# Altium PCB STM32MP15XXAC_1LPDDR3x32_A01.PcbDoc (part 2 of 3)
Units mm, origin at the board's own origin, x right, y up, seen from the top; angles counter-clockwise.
Board outline 89 x 120 mm, 6 copper layers (Top Layer, Signal Layer 1, Signal Layer 2, Signal Layer 3, Signal Layer 4, Bottom Layer), stack 1.556 mm thick; 93 components, 99 nets, 917 pads, 464 vias.
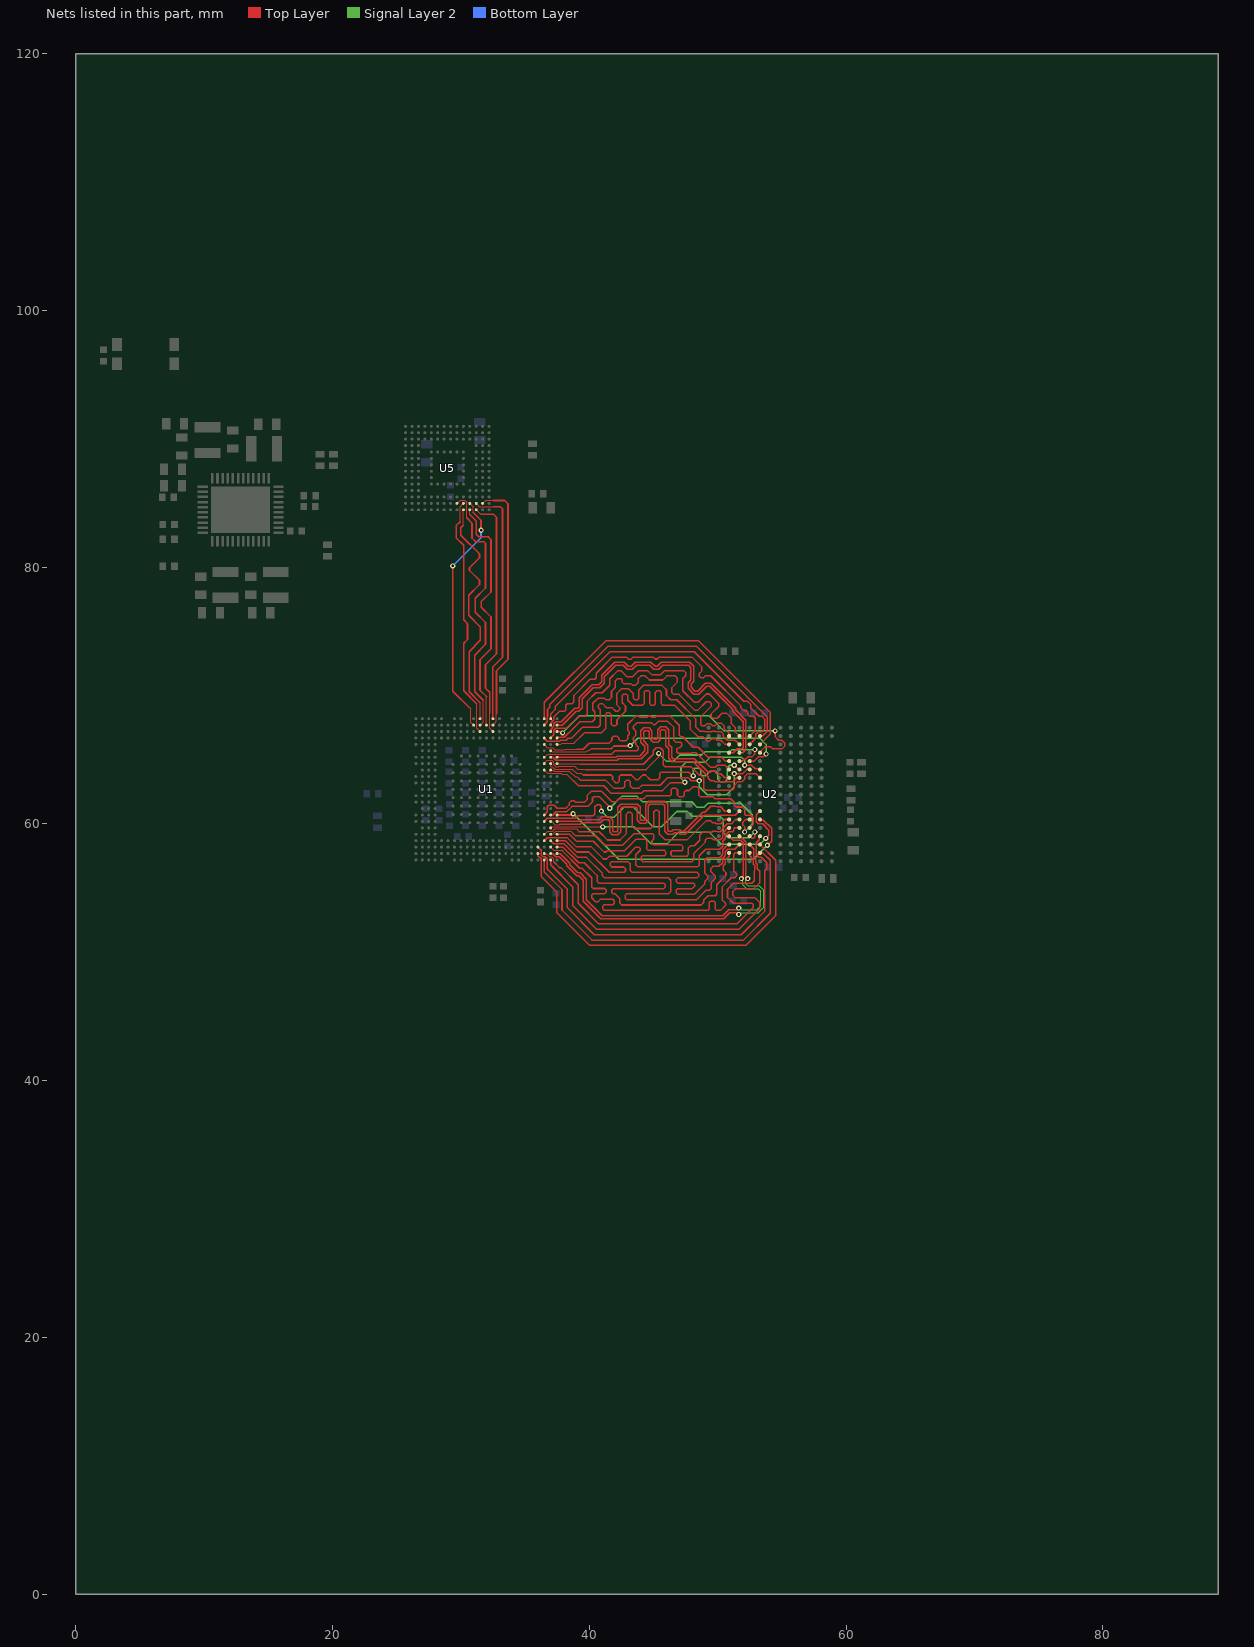
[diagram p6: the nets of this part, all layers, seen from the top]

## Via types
v1: diameter 0.4, hole 0.2, Top Layer to Bottom Layer, tented both sides, 258 vias
v2: diameter 0.25, hole 0.1, Top Layer to Signal Layer 1, tented top, 105 vias
v3: diameter 0.6, hole 0.3, Top Layer to Bottom Layer, tented both sides, 95 vias
v4: diameter 0.25, hole 0.1, Top Layer to Signal Layer 1, tented both sides, 6 vias

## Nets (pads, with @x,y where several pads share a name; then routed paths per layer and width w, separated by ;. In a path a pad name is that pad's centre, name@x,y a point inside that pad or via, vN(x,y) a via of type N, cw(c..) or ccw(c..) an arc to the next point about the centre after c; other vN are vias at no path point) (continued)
DDR_DQ1: U1.F22 U2.N9 | length 19.7
  Top Layer w0.09: U1.F22@37,65.7 37.089,65.611 39.773,65.611 39.908,65.746 40.055,65.746 40.17,65.861
  Top Layer w0.12: 40.17,65.861 41.711,65.861 41.925,66.075 43.175,66.075 v1(43.2,66.1) ; U2.N9@52.5,64.9 52.847,64.9 53.172,65.225 53.55,65.225 v1(53.775,65.45)
  Signal Layer 2 w0.12: v1(43.2,66.1) 43.775,66.675 53.3,66.675 53.775,66.2 v1(53.775,65.45)
DDR_DQ2: U1.H21 U2.N10 | length 20.1
  Top Layer w0.09: U1.H21@36.5,64.7 36.75,64.95 37.1,64.95 37.25,64.8 37.25,64.599 37.398,64.451 37.601,64.451 37.646,64.496 38.885,64.496 39.105,64.276 39.635,64.276 39.676,64.235
  Top Layer w0.12: 39.676,64.235 44.425,64.235 45.4,65.21 v1(45.4,65.5) v1@45.4,65.525 ; U2.N10@51.7,64.9 51.916,64.9 52.041,65.025 52.15,65.025 52.35,65.225 52.675,65.225 52.9,65.45 v1(52.9,65.8)
  Signal Layer 2 w0.12: v1(45.4,65.5) 46.025,64.875 46.55,64.875 47.05,65.375 48.75,65.375 48.991,65.616 50.941,65.616 51.125,65.8 v1(52.9,65.8)
DDR_DQ3: U1.E21 U2.N11 | length 19
  Top Layer w0.09: U1.E21@36.5,66.196 36.75,65.946 37.163,65.946 37.328,65.781 38.131,65.781 38.171,65.821 39.046,65.821
  Top Layer w0.12: 39.046,65.821 39.536,65.821 39.995,66.28 ; 39.995,66.281 41.537,66.281 41.775,66.519 41.775,66.725 41.875,66.825 42.2,66.825 42.3,66.725 42.3,66.598 42.403,66.495 42.875,66.495 43,66.62 43,66.869 43.128,66.997 43.128,67.153 43.005,67.276 43.005,67.774 43.641,68.41 43.85,68.41 43.95,68.31 44.485,68.31 44.585,68.41 44.79,68.41 44.89,68.31 45.111,68.31 45.211,68.41 46.299,68.41 47.02,67.689 47.02,66.925 47.15,66.795 47.279,66.795 48.104,65.97 48.492,65.97 49.277,65.185 49.901,65.185 49.936,65.22 50.28,65.22 50.6,64.9 U2.N11@50.9,64.9
DDR_DQ4: U1.J21 U2.M8 | length 20.5
  Top Layer w0.09: U1.J21@36.5,64.196 36.755,63.941 37.82,63.941 37.87,63.891 38.259,63.891 38.775,63.375
  Top Layer w0.12: 38.775,63.375 39.175,62.975 41.127,62.975 41.722,62.38 44.056,62.38 44.281,62.605 45.711,62.605 46.301,63.195 47.395,63.195 v1(47.45,63.25) ; v1(52.1,64.575) 52.65,64.575 52.925,64.3 53.25,64.3 U2.M8@53.3,64.25
  Signal Layer 2 w0.12: v1(47.45,63.25) 47.15,63.55 47.15,64.425 47.525,64.8 49.011,64.8 49.399,65.189 51.886,65.189 52.1,64.975 v1(52.1,64.575)
DDR_DQ5: U1.J22 U2.M9 | length 19.6
  Top Layer w0.09: U1.J22@37,64.186 37.183,64.186 37.258,64.111 38.449,64.111 38.895,63.665 39.079,63.665 39.194,63.55
  Top Layer w0.12: 39.194,63.55 39.349,63.395 41.301,63.395 41.896,62.8 42.65,62.8 42.77,62.92 42.77,63.295 42.87,63.395 43.105,63.395 43.2,63.3 43.2,62.95 43.35,62.8 43.882,62.8 44.107,63.025 45.525,63.025 46.115,63.615 47.71,63.615 47.95,63.375 v1(48.575,63.375) ; v1(51.3,63.925) 51.959,63.925 52.284,64.25 U2.M9@52.5,64.25
  Signal Layer 2 w0.12: v1(48.575,63.375) 48.575,62.9 49.2,62.275 50.7,62.275 51.3,62.875 v1(51.3,63.925)
DDR_DQ6: U1.H22 U2.M10 | length 20
  Top Layer w0.09: U1.H22@37,64.7 37,64.5 37.06,64.44 37.11,64.44 37.174,64.376 37.233,64.376 37.328,64.281 38.69,64.281 39.015,63.955 39.383,63.955 39.523,63.815
  Top Layer w0.12: 39.523,63.815 41.71,63.815 41.815,63.71 41.815,63.475 42.07,63.22 42.225,63.22 42.35,63.345 42.35,63.7 42.465,63.815 43.279,63.815 43.649,63.445 43.795,63.445 44.165,63.815 44.385,63.815 44.755,63.445 45.351,63.445 45.503,63.597 45.5,63.6 45.5,63.925 45.61,64.035 47.75,64.035 ; 47.751,64.036 v1@48.044,63.744 ; v1(51.3,64.575) 51.625,64.25 U2.M10@51.7,64.25
  Signal Layer 2 w0.12: v1(48.1,63.75) 48.1,64.223 48.227,64.35 48.575,64.35 48.7,64.225 48.7,63.875 48.825,63.75 49.05,63.75 49.425,64.125 49.861,64.125 50.025,63.961 50.025,63.475 50.225,63.275 50.55,63.275 50.75,63.475 50.75,64.375 50.95,64.575 v1(51.3,64.575)
DDR_DQ7: U1.G21 U2.M11 | length 20.7
  Top Layer w0.09: U1.G21@36.515,65.196 36.76,65.441 40.15,65.441
  Top Layer w0.12: 40.15,65.441 41.74,65.441 42.004,65.705 43.725,65.705 43.825,65.805 43.825,65.988 43.61,66.203 43.61,66.375 43.425,66.56 43.425,66.7 43.61,66.885 43.61,67.265 43.425,67.45 43.425,67.6 43.715,67.89 44.848,67.89 44.998,67.74 45.135,67.74 45.385,67.99 46.125,67.99 46.6,67.515 46.6,66.53 46.755,66.375 47.105,66.375 47.215,66.265 47.215,66.09 47.075,65.95 46.945,65.95 46.82,65.825 46.82,65.625 46.939,65.506 47.976,65.506 48.02,65.55 48.316,65.55 49.35,64.516 49.451,64.415 49.815,64.415 49.975,64.575 50.575,64.575 U2.M11@50.9,64.25
DDR_DQ8: U1.T21 U2.E9 | length 22.4
  Top Layer w0.1: U1.T21@36.5,60.7 36.75,60.95 36.75,61.35 36.85,61.45 37.29,61.45 37.525,61.215 ; 52.175,60.675 52.585,60.675 52.79,60.47 52.79,59.99 U2.E9@52.5,59.7
  Top Layer w0.12: 37.525,61.215 38.175,61.215 38.435,61.475 38.435,61.631 38.614,61.81 38.825,61.81 38.935,61.7 39.63,61.7 39.835,61.905 39.835,62.21 40.18,62.555 40.953,62.555 41.792,61.717 42.062,61.717 42.305,61.96 44.23,61.96 44.455,62.185 46.285,62.185 46.375,62.275 46.375,62.675 46.475,62.775 46.775,62.775 46.875,62.675 46.875,62.25 46.99,62.135 47.325,62.135 47.39,62.2 47.39,62.465 47.535,62.61 47.785,62.61 48.079,62.904 48.4,62.904 48.516,62.788 48.516,62.284 48.665,62.135 49.63,62.135 ; 49.657,62.11 49.632,62.135 49.63,62.135 ; 51.305,61.465 51.305,61.698 51.028,61.975 49.79,61.975 49.63,62.135 ; 51.307,61.463 51.445,61.325 51.9,61.325 52.1,61.125 52.1,60.75 52.175,60.675
DDR_DQ9: U1.U21 U2.D9 | length 21.8
  Top Layer w0.1: U1.U21@36.5,60.196 36.502,60.198 36.75,60.446 38.9,60.446 39.104,60.65 40.3,60.65 40.45,60.8 40.45,61.332 40.613,61.496 40.825,61.496 40.95,61.371 v1(40.95,61)
  Top Layer w0.12: U2.D9@52.5,59.05 52.675,58.875 52.8,58.875 52.9,58.975 v1(52.9,59.375)
  Signal Layer 2 w0.12: v1(40.95,61) 41.425,60.525 41.925,60.525 42.7,61.3 43.45,61.3 44.95,59.8 45.65,59.8 46.825,60.975 47.65,60.975 48.025,60.6 50.175,60.6 50.45,60.325 50.45,59.3 50.825,58.925 52.45,58.925 v1(52.9,59.375)
DDR_DQ10: U1.T22 U2.F9 | length 21.2
  Top Layer w0.1: U1.T22@37,60.696 37.15,60.696 ; 37.15,60.696 37.409,60.956 37.67,60.956
  Top Layer w0.12: 37.67,60.956 38.24,60.956 38.655,61.37 39.894,61.37 40.255,61.731 40.255,62.036 40.354,62.135 40.779,62.135 41.6,61.314 v1(41.6,61.225) ; v1(52.1,59.375) 52.1,59.8 51.95,59.95 51.95,60.125 52.175,60.35 U2.F9@52.5,60.35
  Signal Layer 2 w0.12: v1(41.6,61.225) 42.525,62.15 43.725,62.15 44.15,61.725 47.987,61.725 48.4,61.312 48.937,61.312 49.25,61.625 51.8,61.625 52.7,60.725 52.7,59.975 v1(52.1,59.375)
DDR_DQ11: U1.W21 U2.F11 | length 21.8
  Top Layer w0.09: U1.W21@36.5,59.196 36.502,59.198 36.755,59.451 37.168,59.451 37.328,59.611 39.014,59.611 39.175,59.45
  Top Layer w0.12: 39.175,59.45 39.225,59.4 40.775,59.4 41.42,58.755 42.398,58.755 42.9,59.257 42.9,60.775 43.035,60.91 43.215,60.91 43.335,60.79 43.335,59.84 43.526,59.649 44.774,59.649 45.025,59.9 45.025,60.95 45.135,61.06 45.35,61.06 45.46,60.95 45.46,59.215 45.885,58.79 47.652,58.79 49.127,60.265 49.432,60.265 49.582,60.115 49.81,60.115 49.9,60.025 50.25,60.025 50.575,60.35 U2.F11@50.9,60.35
DDR_DQ12: U1.W23 U2.E11 | length 21.4
  Top Layer w0.1: 49.197,58.9 49.561,58.9 49.701,58.76 50.22,58.76 50.39,58.93 50.39,59.297 50.793,59.7 U2.E11@50.9,59.7
  Top Layer w0.12: U1.W23@37.5,59.186 38.481,59.186 39.007,58.66 40.315,58.66 41.156,57.819 41.306,57.819 41.402,57.915 42.746,57.915 43.641,58.809 44.366,58.809 44.47,58.705 44.47,58.055 44.575,57.95 45.85,57.95 45.95,57.85 45.95,57.625 45.85,57.525 44.145,57.525 44.045,57.425 44.045,57.175 44.145,57.075 48.025,57.075 48.15,57.2 48.15,57.696 49.02,58.566 49.02,58.73 49.191,58.9
DDR_DQ13: U1.T23 U2.F8 | length 21
  Top Layer w0.1: U2.F8@53.3,60.35 53.35,60.3 53.558,60.3 54.2,59.658 54.2,58.675 v1(53.875,58.35)
  Top Layer w0.12: U1.T23@37.5,60.7 38.65,60.7 v1(38.75,60.8)
  Signal Layer 2 w0.12: v1(38.75,60.8) 42.3,57.25 52.775,57.25 v1(53.875,58.35)
DDR_DQ14: U1.W22 U2.F10 | length 20.9
  Top Layer w0.09: U1.W22@37,59.196 37.153,59.196 37.398,59.441 38.566,59.441 38.738,59.269
  Top Layer w0.1: 49.525,59.365 49.605,59.445 49.905,59.445 49.96,59.39 50.2,59.39 50.39,59.58 50.39,59.681 50.734,60.025
  Top Layer w0.12: 38.738,59.269 38.926,59.08 40.501,59.08 41.246,58.335 42.572,58.335 43.467,59.229 44.936,59.229 45.04,59.125 45.04,58.85 44.89,58.7 44.89,58.485 45.005,58.37 47.18,58.37 47.3,58.25 47.3,58.025 47.2,57.925 46.475,57.925 46.37,57.82 46.37,57.6 46.475,57.495 47.595,57.495 47.73,57.63 47.73,58.155 47.89,58.315 48.175,58.315 48.6,58.74 48.6,59.144 48.821,59.365 49.525,59.365 ; 50.734,60.025 51.075,60.025 51.4,60.35 U2.F10@51.7,60.35
DDR_DQ15: U1.Y21 U2.E10 | length 20.4
  Top Layer w0.1: U1.Y21@36.5,58.696 36.502,58.698 36.75,58.946 37.675,58.946 ; 49.074,58.04 50.15,58.04 50.39,58.28 50.39,58.647 50.59,58.847 50.59,59.15 50.85,59.41 51.185,59.41 51.275,59.5 51.275,59.625 51.35,59.7 U2.E10@51.7,59.7
  Top Layer w0.12: 37.675,58.946 38.269,58.946 38.974,58.24 40.141,58.24 41.106,57.275 41.356,57.275 41.576,57.495 42.92,57.495 43.625,58.2 43.875,58.2 43.975,58.1 43.975,57.949 43.625,57.599 43.625,56.825 43.795,56.655 48.43,56.655 48.57,56.795 48.57,57.522 49.074,58.026
DDR_DQ16: U1.B22 U2.T9 | length 23.9
  Top Layer w0.1: U1.B22@37,67.7 37,67.854 37.25,68.104 37.25,68.35
  Top Layer w0.12: 37.25,68.353 37.668,68.771 38.062,68.771 38.175,68.884 38.175,69.25 38.284,69.359 38.65,69.359 38.81,69.519 38.81,70.008 40.067,71.265 40.425,71.265 40.55,71.39 40.55,71.748 41.802,73 42.905,73 43.065,72.84 43.26,72.84 43.42,73 44.98,73 45.131,72.849 45.301,72.849 45.451,73 48.007,73 48.775,72.232 48.775,71.925 48.563,71.713 48.563,71.512 48.7,71.375 48.885,71.375 49.06,71.55 49.457,71.55 51.815,69.192 51.815,69.051 52.026,68.84 52.235,68.84 52.35,68.725 52.35,68.516 52.458,68.408 52.767,68.408 52.935,68.24 52.935,67.285 U2.T9@52.5,66.85
DDR_DQ17: U1.D22 U2.T10 | length 24.6
  Top Layer w0.1: U1.D22@37,66.7 37.25,66.95 37.25,67.296 37.404,67.45 38.226,67.45
  Top Layer w0.12: 38.226,67.45 39.157,68.381 39.656,68.381 39.86,68.585 39.86,69.573 40.502,70.215 41.008,70.215 41.6,70.807 41.6,71.313 42.212,71.925 42.495,71.925 42.95,71.47 43.375,71.47 43.855,71.95 44.545,71.95 44.86,71.635 45.571,71.635 45.886,71.95 47.35,71.95 47.51,71.79 47.51,71.55 47.294,71.334 47.294,70.385 48.204,69.475 48.47,69.475 49.12,70.125 49.348,70.125 50.1,69.373 50.1,69.178 49.486,68.564 49.486,68.379 49.625,68.24 49.965,68.24 50.36,68.635 50.699,68.635 51.05,68.284 51.05,67.841 51.38,67.511 51.38,67.17 U2.T10@51.7,66.85
DDR_DQ18: U1.D23 U2.T11 | length 24.4
  Top Layer w0.1: U1.D23@37.5,66.7 37.5,66.74 38.06,66.74 38.37,67.05
  Top Layer w0.12: 38.375,67.05 39.286,67.961 40.246,67.961 40.435,68.15 40.435,68.741 40.28,68.896 40.28,69.399 40.676,69.795 41.199,69.795 41.309,69.684 41.559,69.684 41.735,69.86 41.735,70.348 42.02,70.633 42.02,71.139 42.197,71.316 42.491,71.316 42.591,71.215 42.591,71.024 42.675,70.94 43.253,70.94 43.371,70.821 43.634,70.821 43.824,71.012 43.824,71.326 44.029,71.53 44.371,71.53 44.686,71.215 45.745,71.215 46.06,71.53 46.695,71.53 46.874,71.351 46.874,71.057 46.44,70.623 46.44,70.225 46.575,70.09 46.995,70.09 48.21,68.875 48.464,68.875 49.114,69.525 49.354,69.525 49.489,69.39 49.489,69.161 48.7,68.372 48.7,67.75 48.8,67.65 48.997,67.65 49.167,67.82 49.433,67.82 49.598,67.655 49.802,67.655 49.985,67.838 50.313,67.838 50.5,67.65 50.5,67.447 50.9,67.047 U2.T11@50.9,66.85
DDR_DQ19: U1.B21 U2.T8 | length 24.7
  Top Layer w0.1: U1.B21@36.5,67.696 36.502,67.698 36.75,67.946 36.75,68.371
  Top Layer w0.12: 36.75,68.371 36.75,68.919 36.92,69.089 36.92,69.306 41.454,73.84 48.355,73.84 53.88,68.315 53.88,67.23 53.525,66.875 U2.T8@53.3,66.875
DDR_DQ20: U1.A21 U2.R8 | length 26
  Top Layer w0.12: U1.A21@36.5,68.196 U1.A21@36.5,68.2 36.5,69.48 41.28,74.26 48.529,74.26 54.1,68.689 54.1,67 U2.R8@53.3,66.2
DDR_DQ21: U1.E23 U2.R11 | length 24.5
  Top Layer w0.09: U1.E23@37.5,66.196 37.796,66.196 37.9,66.3 38.825,66.3
  Top Layer w0.12: 38.825,66.3 39.646,67.121 40.983,67.121 41.275,67.413 41.275,68.55 41.375,68.65 41.6,68.65 41.725,68.525 41.725,67.775 41.835,67.665 42.065,67.665 42.165,67.765 42.165,68.122 42.825,68.782 42.825,69.2 42.575,69.45 42.575,70 42.675,70.1 42.905,70.1 43.005,70 43.005,69.645 43.4,69.25 44.15,69.25 44.27,69.37 44.27,70.27 44.375,70.375 44.625,70.375 44.725,70.275 44.725,69.35 44.825,69.25 45.05,69.25 45.16,69.36 45.16,70.26 45.275,70.375 45.5,70.375 45.6,70.275 45.6,69.375 45.725,69.25 46.647,69.25 47.86,68.037 47.86,67.402 48.452,66.81 48.84,66.81 49.191,66.459 49.361,66.459 49.539,66.636 49.861,66.636 49.972,66.525 50.25,66.525 50.575,66.2 U2.R11@50.9,66.2
DDR_DQ22: U1.D21 U2.R10 | length 23.7
  Top Layer w0.1: U1.D21@36.5,66.696 36.746,66.45 37.686,66.45 37.776,66.54 38.215,66.54 38.341,66.666 38.597,66.666
  Top Layer w0.12: 38.597,66.666 39.472,67.541 40.696,67.541 40.855,67.7 40.855,68.915 40.7,69.07 40.7,69.225 40.85,69.375 41.025,69.375 41.33,69.07 41.774,69.07 42.059,68.784 42.234,68.784 42.366,68.916 42.366,69.066 42.155,69.276 42.155,70.174 42.501,70.52 43.079,70.52 43.425,70.174 43.425,69.819 43.574,69.67 43.745,69.67 43.85,69.775 43.85,70.444 44.201,70.795 45.674,70.795 46.02,70.449 46.02,70.005 46.355,69.67 46.821,69.67 48.28,68.211 48.28,67.576 48.626,67.23 49.014,67.23 49.069,67.175 49.503,67.175 49.563,67.235 49.818,67.235 49.878,67.175 50.275,67.175 50.45,67 50.45,66.825 50.75,66.525 51.375,66.525 U2.R10@51.7,66.2
DDR_DQ23: U1.A22 U2.R9 | length 24.1
  Top Layer w0.12: U1.A22@37,68.196 U1.A22@37,68.2 37,68.575 37.34,68.915 37.34,69.132 41.628,73.42 48.181,73.42 52.038,69.564 52.32,69.564 52.568,69.316 52.568,69.057 53.24,68.385 53.449,68.385 53.66,68.174 53.66,67.407 53.433,67.18 53.177,67.18 52.98,66.983 52.98,66.68 U2.R9@52.5,66.2
DDR_DQ24: U1.Y23 U2.C11 | length 28.6
  Top Layer w0.1: 48.98,57.19 49.18,57.39 50.15,57.39 50.39,57.63 50.39,57.997 50.793,58.4 U2.C11@50.9,58.4
  Top Layer w0.12: U1.Y23@37.504,58.696 38.154,58.696 39.03,57.82 39.967,57.82 41.552,56.235 42.735,56.235 42.825,56.325 42.825,56.525 42.7,56.65 41.75,56.65 41.65,56.75 41.65,56.975 41.75,57.075 43.025,57.075 43.2,56.9 43.2,56.375 43.34,56.235 48.4,56.235 48.525,56.11 48.525,55.925 48.425,55.825 46.925,55.825 46.795,55.695 46.795,55.5 46.895,55.4 48.106,55.4 48.206,55.3 48.206,55.156 48,54.95 46.87,54.95 46.77,54.85 46.77,54.63 46.87,54.53 48.198,54.53 48.99,55.322 48.99,55.519 49.248,55.777 49.248,55.928 48.99,56.186 48.99,57.186
DDR_DQ25: U1.Y22 U2.C10 | length 27.9
  Top Layer w0.1: U1.Y22@37,58.696 37.245,58.451 ; 37.245,58.446 37.75,58.446 ; 50.105,56.695 50.39,56.98 50.39,57.34 50.59,57.54 50.59,57.85 50.78,58.04 51.34,58.04 U2.C10@51.7,58.4
  Top Layer w0.12: 37.75,58.446 38.058,58.446 39.104,57.4 39.793,57.4 41.03,56.163 41.03,55.975 41.19,55.815 46.16,55.815 46.35,55.625 46.35,54.75 46.15,54.55 42.9,54.55 42.79,54.44 42.79,54.225 42.905,54.11 48.372,54.11 49.102,54.84 49.375,54.84 49.51,54.975 49.51,55.445 49.825,55.76 49.825,55.945 49.47,56.3 49.47,56.525 49.64,56.695 50.105,56.695
DDR_DQ26: U1.AB21 U2.B9 | length 27.9
  Top Layer w0.09: U1.AB21@36.5,57.7 36.661,57.7 36.921,57.44 37.099,57.44 37.25,57.289 37.25,57.061
  Top Layer w0.1: U2.B9@52.5,57.75 52.5,57.525 52.79,57.235 52.79,56.88 52.9,56.77 52.9,56.393 52.845,56.338 52.845,56.175
  Top Layer w0.12: 37.243,57.054 37.687,56.609 37.803,56.609 39.14,55.273 39.14,53.82 40.74,52.22 51.5,52.22 52.79,53.51 52.79,53.705 52.675,53.82 51.227,53.82 50.77,54.277 50.77,54.923 51.237,55.39 52.66,55.39 52.845,55.575 52.845,56.175
DDR_DQ27: U1.AB20 U2.C8 | length 30.3
  Top Layer w0.1: U1.AB20@36,57.7 36,57.546 36.25,57.296 36.25,56.925
  Top Layer w0.12: 36.25,56.925 36.25,55.925 37.46,54.715 37.46,53.124 40.044,50.54 52.196,50.54 54.525,52.869 54.525,57.175 U2.C8@53.3,58.4
DDR_DQ28: U1.AC22 U2.C9 | length 29
  Top Layer w0.1: U2.C9@52.5,58.4 52.81,58.09 52.81,57.498 52.99,57.318 52.99,56.963 53.1,56.853 53.1,56.5 53.265,56.335
  Top Layer w0.12: U1.AC22@37,57.2 37,56.819 38.72,55.099 38.72,53.646 40.566,51.8 51.674,51.8 53.265,53.391 53.265,53.899 52.924,54.24 51.401,54.24 51.19,54.451 51.19,54.749 51.411,54.97 52.834,54.97 53.265,55.401 53.265,56.335
DDR_DQ29: U1.AC21 U2.B8 | length 27.7
  Top Layer w0.12: U1.AC21@36.5,57.2 36.5,56.269 37.88,54.889 37.88,53.298 40.218,50.96 52.022,50.96 54.105,53.043 54.105,57.17 53.525,57.75 U2.B8@53.3,57.75
DDR_DQ30: U1.AA23 U2.B11 | length 27.6
  Top Layer w0.1: 50.44,56.45 50.44,56.747 50.61,56.917 50.61,57.22 50.78,57.39 50.79,57.39 50.9,57.5 U2.B11@50.9,57.75
  Top Layer w0.12: U1.AA23@37.5,58.196 37.969,58.196 39.184,56.98 39.619,56.98 40.61,55.989 40.61,55.535 40.75,55.395 45.825,55.395 45.93,55.29 45.93,55.1 45.8,54.97 41.875,54.97 41.75,54.845 41.75,54.675 41.855,54.57 41.999,54.57 42.37,54.199 42.37,53.855 42.535,53.69 48.72,53.69 48.93,53.9 48.93,54.074 49.276,54.42 49.825,54.42 49.93,54.525 49.93,55.271 50.654,55.996 50.654,56.22 50.44,56.434 50.44,56.45
DDR_DQ31: U1.AA22 U2.B10 | length 27.5
  Top Layer w0.09: U1.AA22@37,58.196 37.25,57.946 37.879,57.946
  Top Layer w0.12: 37.879,57.946 39.265,56.56 39.445,56.56 40.19,55.815 40.19,55.085 40.3,54.975 41.205,54.975 41.33,54.85 41.33,54.705 41.2,54.575 40.3,54.575 40.19,54.465 40.19,54.26 40.5,53.95 40.675,53.95 40.875,54.15 41.825,54.15 41.95,54.025 41.95,53.825 41.825,53.7 41.15,53.7 41.038,53.588 41.038,53.412 41.175,53.275 41.175,53.27 49.245,53.27 49.35,53.375 49.35,53.9 49.45,54 49.7,54 49.8,53.9 49.8,53.375 49.905,53.27 50.215,53.27 50.625,53.68 50.625,53.828 50.35,54.103 50.35,55.097 51.063,55.81 51.33,55.81 51.475,55.955 51.475,56.124 51.25,56.349 51.25,57.65 51.35,57.75 U2.B10@51.7,57.75
DDR_DQM0: U1.H23 U2.L8 | length 19.9
  Top Layer w0.09: U1.H23@37.5,64.696 39.3,64.696
  Top Layer w0.12: 39.3,64.655 44.211,64.655 44.98,65.424 44.98,65.699 45.226,65.945 45.524,65.945 45.77,65.699 45.77,64.605 45.919,64.456 47.925,64.456 48.586,63.795 48.705,63.795 48.936,63.564 48.936,62.764 49.075,62.625 51.125,62.625 51.3,62.8 51.3,63.025 51.55,63.275 51.875,63.275 52.125,63.525 52.125,63.725 52.325,63.925 52.975,63.925 U2.L8@53.3,63.6
DDR_DQM1: U1.V22 U2.G8 | length 21.3
  Top Layer w0.09: U1.V22@37,59.696 37.002,59.698 37.085,59.781 v1@41.05,59.781
  Top Layer w0.1: U2.G8@53.3,61 53.01,60.71 53.01,60.165 53.165,60.01 53.51,60.01 54,59.52 54,59.125 v1(53.75,58.875)
  Signal Layer 2 w0.12: v1(41.05,59.775) 43.5,59.775 44.825,58.45 46.05,58.45 46.975,59.375 49.325,59.375 50.275,58.425 53.3,58.425 v1(53.75,58.875)
DDR_DQM2: U1.C23 U2.P8 | length 21.8
  Top Layer w0.12: U1.C23@37.5,67.2 37.825,67.2 v1(37.925,67.1) ; U2.P8@53.3,65.55 53.3,65.609 53.62,65.929 ; 53.622,65.928 53.719,66.025 54.125,66.025 54.275,65.875 55.05,65.875 55.22,66.045 55.22,66.333 55.023,66.53 54.767,66.53 54.475,66.822 v1(54.475,67.25)
  Signal Layer 2 w0.12: v1(37.925,67.1) 39.25,68.425 49.325,68.425 50.505,67.245 v1@54.28,67.245
DDR_DQM3: U1.AA20 U2.D8 | length 29.3
  Top Layer w0.1: U1.AA20@36,58.2 36.25,57.95 36.25,57.604 36.399,57.455 36.591,57.455 36.745,57.301 36.745,56.88 ; U2.D8@53.3,59.05 53.25,59 53.25,58.79 53.01,58.55 53.01,57.63 53.215,57.425 53.385,57.425 53.825,56.985 53.825,56.516 53.685,56.376
  Top Layer w0.12: 36.745,56.88 36.745,56.48 38.3,54.925 38.3,53.472 40.392,51.38 51.848,51.38 53.685,53.217 53.685,56.376
DDR_DQS0_N: U1.G23 U2.L11 | length 20
  Top Layer w0.1: U1.G23@37.5,65.196 42.075,65.196 42.174,65.295 43.946,65.295 44.338,65.687 44.338,66.055 44.02,66.373 44.02,67.27 44.23,67.48 44.678,67.48 44.888,67.27 44.888,66.763 45.065,66.585 45.235,66.585 45.32,66.67 45.32,67.345 45.555,67.58 45.955,67.58 46.19,67.345 46.19,66.184 46.41,65.964 46.41,65.206 46.52,65.096 48.19,65.096 49.271,64.015 49.42,64.015 49.5,64.095 49.78,64.095 ; 49.78,64.095 49.95,63.925 50.25,63.925 50.575,63.6 U2.L11@50.9,63.6
DDR_DQS0_P: U1.G22 U2.L10 | length 21.6
  Top Layer w0.1: U1.G22@37,65.2 37.15,65.2 37.4,64.95 37.57,64.95 37.575,64.955 ; 37.583,64.966 42.17,64.966 42.269,65.065 44.041,65.065 44.568,65.592 44.568,66.15 44.25,66.468 44.25,67.175 44.325,67.25 44.583,67.25 44.658,67.175 44.658,66.667 44.97,66.355 45.33,66.355 45.55,66.575 45.55,67.25 45.65,67.35 45.86,67.35 45.96,67.25 45.96,66.089 46.18,65.869 46.18,65.111 46.425,64.866 48.095,64.866 49.275,63.686 49.275,63.58 49.48,63.375 49.73,63.375 49.795,63.31 51.21,63.31 51.5,63.6 U2.L10@51.7,63.6
DDR_DQS1_N: U1.U23 U2.G11 | length 22
  Top Layer w0.1: U1.U23@37.5,60.206 39.195,60.206 39.324,60.335 40.77,60.335 40.98,60.546 41.58,60.546 41.815,60.31 41.815,59.485 41.905,59.395 42.133,59.395 42.225,59.487 42.225,61.3 42.475,61.55 43.75,61.55 43.975,61.325 43.975,60.375 44.061,60.289 44.289,60.289 44.385,60.385 44.385,61.535 44.625,61.775 45.85,61.775 46.1,61.525 46.1,59.525 46.195,59.43 46.43,59.43 46.55,59.55 47.055,59.55 47.175,59.43 47.38,59.43 48.855,60.905 48.985,60.905 49.48,61.4 49.84,61.4 49.915,61.325 50.25,61.325 50.575,61 U2.G11@50.9,61
DDR_DQS1_P: U1.U22 U2.G10 | length 23.2
  Top Layer w0.09: U1.U22@37,60.196 37.088,60.196 37.333,59.951 37.676,59.951 37.701,59.976
  Top Layer w0.1: 37.701,59.976 39.29,59.976 39.42,60.105 40.865,60.105 41.075,60.316 41.484,60.316 41.585,60.215 41.585,59.39 41.81,59.165 42.228,59.165 42.455,59.392 42.455,61.205 42.57,61.32 43.655,61.32 43.745,61.23 43.745,60.28 43.966,60.059 44.384,60.059 44.615,60.29 44.615,61.44 44.72,61.545 45.755,61.545 45.87,61.43 45.87,59.43 46.1,59.2 46.525,59.2 46.645,59.32 46.96,59.32 47.08,59.2 47.475,59.2 48.95,60.675 51.375,60.675 U2.G10@51.7,61
DDR_DQS2_N: U1.B23 U2.P11 | length 24.6
  Top Layer w0.1: U1.B23@37.5,67.7 37.897,67.7 38.987,68.791 39.191,68.791 39.45,69.05 39.45,69.743 40.332,70.625 40.838,70.625 41.19,70.977 41.19,71.483 42.067,72.36 42.64,72.36 42.955,72.045 43.37,72.045 43.685,72.36 44.715,72.36 45.03,72.045 45.401,72.045 45.716,72.36 47.742,72.36 47.92,72.182 47.92,71.22 47.704,71.004 47.704,70.555 48.134,70.125 48.54,70.125 49.135,70.72 49.382,70.72 51.175,68.927 51.175,68.786 52,67.961 52,65.975 51.9,65.875 51.525,65.875 51.2,65.55 U2.P11@50.9,65.55
DDR_DQS2_P: U1.C22 U2.P10 | length 25.5
  Top Layer w0.1: U1.C22@37,67.2 37,67.354 37.25,67.604 37.25,67.81 37.39,67.95 ; 37.396,67.95 37.821,67.95 38.892,69.021 39.095,69.021 39.22,69.145 39.22,69.838 40.237,70.855 40.743,70.855 40.96,71.072 40.96,71.578 41.972,72.59 42.735,72.59 43.05,72.275 43.275,72.275 43.59,72.59 44.81,72.59 45.125,72.275 45.306,72.275 45.621,72.59 47.838,72.59 48.15,72.278 48.15,71.125 47.934,70.909 47.934,70.65 48.229,70.355 48.445,70.355 49.04,70.95 49.478,70.95 51.405,69.022 51.405,68.881 52.2,68.086 52.2,65.8 51.95,65.55 U2.P10@51.7,65.55
DDR_DQS3_N: U1.AB23 U2.D11 | length 26.8
  Top Layer w0.1: U1.AB23@37.5,57.7 37.725,57.7 38.48,56.945 38.48,56.838 39.118,56.2 39.296,56.2 39.78,55.716 39.78,54.09 40.765,53.105 40.765,53.1 41.005,52.86 50.385,52.86 50.855,53.33 51.53,53.33 v1(51.65,53.45) ; U2.D11@50.9,59.05 51.225,58.725 51.799,58.725 52,58.524 52,55.9 v1(51.85,55.75)
  Signal Layer 2 w0.09: v1(51.65,53.45) 51.73,53.45 51.85,53.33 53.055,53.33 53.345,53.62 53.345,54.755 53.15,54.95 52.275,54.95 51.97,55.255 51.97,55.63 v1(51.85,55.75) v1@51.85,55.65
DDR_DQS3_P: U1.AB22 U2.D10 | length 27.2
  Top Layer w0.1: U1.AB22@37,57.696 37.146,57.696 37.396,57.446 37.654,57.446 38.25,56.85 38.25,56.743 39.023,55.97 39.2,55.97 39.55,55.62 39.55,53.99 40.91,52.63 50.48,52.63 50.95,53.1 51.5,53.1 v1(51.65,52.95) ; U2.D10@51.7,59.05 51.757,59.05 52.2,58.607 52.2,55.9 v1(52.35,55.75)
  Signal Layer 2 w0.09: v1(51.65,52.95) 51.7,52.95 51.85,53.1 53.15,53.1 53.575,53.525 53.575,54.85 53.245,55.18 52.37,55.18 52.2,55.35 52.2,55.6 v1(52.35,55.75) v1@52.35,55.706
  Bottom Layer w0.1: v1(51.65,52.95) v1@51.687,52.95
eMMC_SDIO2_D0: U1.C13 U5.A3 | length 19.1
  Top Layer w0.09: U5.A3@31.2,84.475 31.55,84.125 ; 32.25,68.625 32.25,67.45 U1.C13@32.5,67.2
  Top Layer w0.13: 31.55,84.125 32.55,84.125 32.775,83.9 32.775,73.25 31.925,72.4 31.925,70.575 32.25,70.25 32.25,68.625
eMMC_SDIO2_D1: U1.B12 U5.A4 | length 19.1
  Top Layer w0.09: 30.7,84.1 U5.A4@30.7,84.475 ; U1.B12@32,67.7 32,69.925
  Top Layer w0.13: 30.7,84.1 31.2,83.6 31.2,82.575 31.4,82.375 32.125,82.375 32.35,82.15 32.35,78.075 31.6,77.325 31.6,76.875 32.35,76.125 32.35,73.65 31.5,72.8 31.5,70.425 32,69.925
eMMC_SDIO2_D2: U1.A11 U5.A5 | length 19
  Top Layer w0.09: 30.2,83.275 U5.A5@30.2,84.475 ; U1.A11@31.5,68.2 31.5,69.45
  Top Layer w0.13: 30.2,83.275 30,83.075 30,82.5 31.45,81.05 31.45,80.725 30.675,79.95 30.675,79.75 31.45,78.975 31.45,78.65 30.625,77.825 30.625,76.25 31.525,75.35 31.525,74.3 30.65,73.425 30.65,70.3 31.5,69.45
eMMC_SDIO2_D3: U1.B13 U5.B2 | length 19.9
  Top Layer w0.09: U5.B2@31.7,84.975 31.725,84.975 31.965,85.215 32.51,85.215 32.525,85.2 ; U1.B13@32.5,67.7 32.75,67.95 32.75,68.6 ; 33.4,85.2 33.425,85.2
  Top Layer w0.13: 32.525,85.2 33.4,85.2 ; 32.775,68.6 32.775,71.941 33.675,72.841 33.675,84.95 33.425,85.2
eMMC_SDIO2_D4: U1.A13 U5.B3 | length 18.9
  Top Layer w0.09: U5.B3@31.2,84.975 31.2,84.965 31.45,84.715 32.515,84.715
  Top Layer w0.13: U1.A13@32.5,68.2 32.5,72.25 33.25,73 33.25,84.55 33.085,84.715 32.515,84.715
eMMC_SDIO2_D5: U1.B10 U5.B4 | length 19.2
  Top Layer w0.09: 30.65,69.075 30.76,68.965 30.76,67.94 U1.B10@31,67.7 ; U5.B4@30.7,84.975 30.95,84.725 30.95,84.275
  Top Layer w0.13: v1(29.375,80.1) 29.375,70.35 30.65,69.075 ; 30.95,84.275 31.575,83.65 v1(31.575,82.875)
  Bottom Layer w0.13: v1(29.375,80.1) 31.575,82.3 v1(31.575,82.875)
eMMC_SDIO2_D6: U1.C11 U5.B5 | length 19
  Top Layer w0.09: 29.95,83.55 29.95,84.725 U5.B5@30.2,84.975 U5.B5@30.2,84.965 ; 31.25,69.35 31.25,67.45 U1.C11@31.5,67.2
  Top Layer w0.13: 29.95,83.55 29.65,83.25 29.65,82.275 30.225,81.7 30.225,75.9 30.525,75.6 30.525,74.375 30.225,74.075 30.225,70.375 31.25,69.35
eMMC_SDIO2_D7: U1.B11 U5.B6 | length 20.7
  Top Layer w0.09: U5.B6@29.7,84.975 29.95,85.225 30.325,85.225 30.45,85.1 30.45,83.85 ; U1.B11@31.5,67.7 31.74,67.94 31.74,69.635
  Top Layer w0.13: 30.45,83.85 30.875,83.425 30.875,82.275 31.175,81.975 31.8,81.975 31.925,81.85 31.925,78.375 31.125,77.575 31.125,76.5 31.925,75.7 31.925,74 31.075,73.15 31.075,70.3 31.74,69.635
